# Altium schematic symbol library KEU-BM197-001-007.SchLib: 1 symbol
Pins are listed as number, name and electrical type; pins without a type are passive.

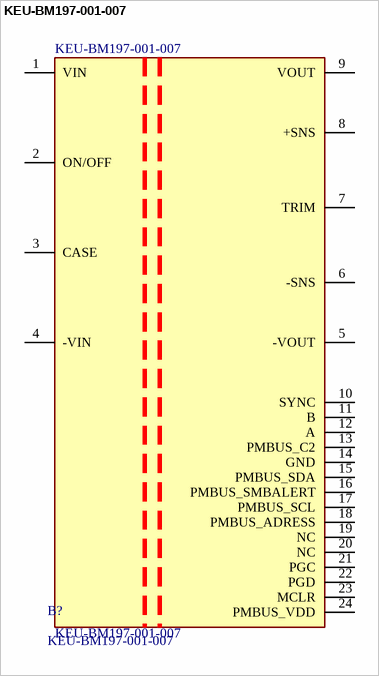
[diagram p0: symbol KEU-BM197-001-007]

## KEU-BM197-001-007
designator B?
16-40Vin XXVout XXXW Isolated Half Brick with Flanged Option; MFG: KOLT
footprint KEU-BM197-001-007
pins: 1 VIN, 2 ON/OFF, 3 CASE, 4 -VIN, 5 -VOUT, 6 -SNS, 7 TRIM, 8 +SNS, 9 VOUT, 10 SYNC, 11 B, 12 A, 13 PMBUS_C2, 14 GND, 15 PMBUS_SDA, 16 PMBUS_SMBALERT, 17 PMBUS_SCL, 18 PMBUS_ADRESS, 19 NC, 20 NC, 21 PGC, 22 PGD, 23 MCLR, 24 PMBUS_VDD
